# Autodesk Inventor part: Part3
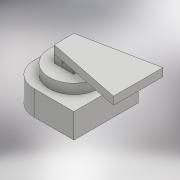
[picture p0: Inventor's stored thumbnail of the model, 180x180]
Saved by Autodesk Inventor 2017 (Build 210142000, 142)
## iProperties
Created: 2016-07
Part Number: Part3
Material: Generic
Document SubType Name: Modeling
Designer: Polytech
Density: 1 g/cm^3
Appearance: Default
Author: Polytech
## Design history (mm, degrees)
sketch "Sketch1"
  geometry: 1 further point
sketch "Sketch2"
  geometry: C1 r 23 at (0, 0); 1 further point
  constraints: 1 centre point, 1 coincident
  dimensions: "d0" = 46 diameter of C1
extrude "Extrusion1" new body sketch "Sketch2" distance "d1" = 18; taper "d2" = 0 deg
sketch "Sketch3"
  geometry: L1 (-11.75, -48.75)-(48.75, -48.75); L2 (48.75, -48.75)-(48.75, 48.75); L3 (48.75, 48.75)-(-11.75, 48.75); L4 (-48.75, 11.75)-(-48.75, -11.75); L5 (-48.75, -48.75)-(48.75, 48.75); L6 (48.75, -48.75)-(-48.75, 48.75); A1 r 37 centre (-11.75, 11.75) between (-11.75, 48.75) and (-48.75, 11.75); A2 r 37 centre (-11.75, -11.75) between (-48.75, -11.75) and (-11.75, -48.75); 1 further point
  constraints: 12 end point, 4 point on circle, 4 point on line, 4 tangent, 2 centre point, 2 midpoint, 2 parallel, 1 equal radius, 1 horizontal, 1 perpendicular
  dimensions: "d3" = 97.5 distance of L6.end L2.end; "d4" = 97.5 distance of L2.end L1.end; "d5" = 37 radius of A1
extrude "Extrusion2" join sketch "Sketch3" distance "d6" = 37.5; taper "d7" = 0 deg
sketch "Sketch4"
  geometry: C1 r 37.5 at (0, 0); 1 further point
  constraints: 1 centre point, 1 coincident
  dimensions: "d8" = 75 diameter of C1
extrude "Extrusion3" join sketch "Sketch4" distance "d9" = 15; taper "d10" = 0 deg
sketch "Sketch5"
  geometry: L1 (-15, -15)-(15, -15); L2 (15, -15)-(15, 15); L3 (15, 15)-(-15, 15); L4 (-15, 15)-(-15, -15); L5 (-15, -15)-(15, 15); L6 (15, -15)-(-15, 15); 1 further point
  constraints: 12 end point, 2 midpoint, 2 parallel, 1 horizontal, 1 perpendicular
  dimensions: "d11" = 30 distance of L3.end L2.end; "d12" = 30 distance of L2.end L1.end
extrude "Extrusion4" join sketch "Sketch5" distance "d13" = 12; taper "d14" = 0 deg
sketch "Sketch6"
  geometry: L1 (-15, -6)-(15, -6); L2 (15, -6)-(15, 6); L3 (15, 6)-(-15, 6); L4 (-15, 6)-(-15, -6); L5 (-15, -6)-(15, 6); L6 (15, -6)-(-15, 6); 1 further point
  constraints: 12 end point, 2 midpoint, 2 parallel, 1 horizontal, 1 perpendicular
  dimensions: "d15" = 30 distance of L3.end L2.end; "d16" = 12 distance of L2.end L1.end
extrude "Extrusion5" cut sketch "Sketch6" distance "d17" = 12; taper "d18" = 0 deg
sketch "Sketch7"
  geometry: L1 (52.5, 0)-(-22.5, 0) reference; C1 r 3 at (15, 6); 1 further point
  constraints: 1 centre point, 1 vertical alignment
  dimensions: "d19" = 3 radius of C1; "d20" = 6 distance from line of C1.centre L1
extrude "Extrusion6" cut sketch "Sketch7" stored distance "d21" = 12; taper "d22" = 0 deg
sketch "Sketch8"
  geometry: L1 (-15, 15)-(-15, -15); L2 (-15, -15)-(97.5, -37.5); L3 (97.5, -37.5)-(97.5, 37.5); L4 (97.5, 37.5)-(-15, 15); 4 further points
  constraints: 8 end point, 2 coincident, 1 horizontal alignment, 1 midpoint, 1 parallel, 1 vertical
  dimensions: "d23" = 75 distance of L2.end L3.end; "d24" = 97.5 distance from line of L3 point (0, 0)
extrude "Extrusion7" join sketch "Sketch8" distance "d25" = 12; taper "d26" = 0 deg
sketch "Sketch9"
  geometry: C1 r 23 at (0, 0); 1 further point
  constraints: 1 centre point, 1 coincident
  dimensions: "d27" = 46 diameter of C1
extrude "Extrusion8" cut sketch "Sketch9" distance "d28" = 24.5; taper "d29" = 0 deg
body "Solid1"
